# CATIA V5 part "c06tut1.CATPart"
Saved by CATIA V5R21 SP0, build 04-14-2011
Part number: Part1
Bounding box of the stored display mesh (mm): x -104.697 to 0, y -66 to 66, z 0 to 107.508
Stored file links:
  D:\CATIA V5R21 E-RESOURCES\CATIA-V5R21\catia-v5r21-prt\c06-catia-v5r21-prt\c05-tut01.CATPart
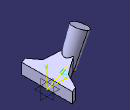
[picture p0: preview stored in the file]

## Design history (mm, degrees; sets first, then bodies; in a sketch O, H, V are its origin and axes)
Body1 (main body)
  Sketch1 on zx-plane, origin (0, 0, 0), H (-1, 0, 0), V (0, 0, 1)
    line L1 (0, 0) -> (53.9276, 26.3023)
    line L2 (53.9276, 26.3023) -> (86.4666, 99.3859)
    point P2 (86.4666, 99.3859)
    length L1 = 60
    angle L1 H = 26
    length L2 = 80
    angle L1 L2 = 140
  Sketch2 on yz-plane, origin (0, 0, 0), H (0, 1, 0), V (0, 0, 1)
    point P1 (55.2864, 0)
    coincidence: P1 H
  Plane1: type 3Points, Element1 Sketch2, Element2 Sketch1.O, Element3 vertex [element of Sketch1 | element of Sketch1]
  Sketch3 on Plane1, origin (0, 0, 0), H (0, -1, 0), V (-0.8988, 0, 0.4384)
    construction line L1 (0, 0) -> (0, 85.3653)
    point P2 (-66, 0)
    line L2 (-66, 0) -> (-65.4759, 10)
    point P3 (-65.4759, 10)
    line L3 (-65.4759, 10) -> (-33, 25)
    point P4 (-33, 25)
    line L4 (-33, 25) -> (-12.1773, 65)
    point P5 (-12.1773, 65)
    point P6 (65.4759, 10)
    point P7 (66, 0)
    line L5 (66, 0) -> (65.4759, 10)
    point P8 (33, 25)
    line L6 (65.4759, 10) -> (33, 25)
    point P9 (12.1773, 65)
    line L7 (33, 25) -> (12.1773, 65)
    line L8 (-66, 0) -> (66, 0)
    line L9 (-12.1773, 65) -> (12.1773, 65)
    axis line L10 (66, 0) -> (66, 58.4906)
    length L8 = 132
    distance P4 P8 = 66
    distance P2 P4 V = 25
    angle L4 L7 = 55
    angle L10 L5 = 3
    distance P2 P3 V = 10
    distance L8 L9 = 65
    vertical: L1 V, L10 V
    coincidence: P2 H
    symmetry: P3 P6 L1, P2 P7 L1, L2 L5 L1, P4 P8 L1, L3 L6 L1, P5 P9 L1, L4 L7 L1
    horizontal: L8 H, L9 H
  Pad1: profile Sketch3, direction along xy-plane, length 28
  Plane2: type Normal, Curve Sketch1, RefPoint Sketch1.P2
  Sketch4 on Plane2, origin (-51.2336, 0, 115.0726), H (0, -1, 0), V (0.9135, 0, 0.4067)
    circle A1 centre (0, -38.5673) radius 17
    point P1 (0, -38.5673)
    reference projected point E1 (0, -38.5673) from Sketch1.P2
    radius A1 = 17
    coincidence: P1 V, P1 E1
  Pad2: profile Sketch4, direction (0.4067, 0, -0.9135), length 85, opposite side up to Plane2
  Draft1: Angle 2, Neutral end face of Pad2, PullDir end face of Pad2, SupportToDraft face of Pad2 from Sketch4.A1
  Sketch5 on zx-plane, origin (0, 0, 0), H (-1, 0, 0), V (0, 0, 1)
    projected line E1 (0, 0) -> (53.9276, 26.3023) from Sketch1.L1
    line L1 (53.9276, 26.3023) -> (94.0424, 45.8675)
    parallelism: L1 E1
  Pocket1: profile Sketch5, direction (0, -1, 0), through (limit type 3), opposite side through (limit type 3)
  Fillet1: radius 12, on edge [face of Pad1 from Sketch3.L3 | face of Pad1 from Sketch3.L2]; edge [face of Pad1 from Sketch3.L3 | face of Pocket1 from Sketch5.E1]; edge [face of Pad1 from Sketch3.L4 | face of Pocket1 from Sketch5.E1]; edge [face of Pocket1 from Sketch5.L1 | face of Pad2 from Sketch4.A1]; edge [face of Pad1 from Sketch3.L7 | face of Pocket1 from Sketch5.E1]; edge [face of Pad1 from Sketch3.L6 | face of Pocket1 from Sketch5.E1]; edge [face of Pad1 from Sketch3.L4 | face of Pad1 from Sketch3.L3]; edge [face of Pad2 from Sketch4.A1 | face of Pad1 from Sketch3.L4]; edge [face of Pad1 from Sketch3.L6 | face of Pad1 from Sketch3.L7]; edge [face of Pad2 from Sketch4.A1 | face of Pad1 from Sketch3.L7]; edge [face of Pad2 from Sketch4.A1 | end face of Pad1]; edge [face of Pad1 from Sketch3.L5 | face of Pad1 from Sketch3.L6]
  Fillet2: radius 3, on edge [end face of Pad1 | face of Fillet1] (x2); edge [face of Fillet1 | face of Fillet1] (x2)
  Shell1: ExtOffset 0, Face (start face of Pad2; face of Pad1 from Sketch3.L8), IntOffset 2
